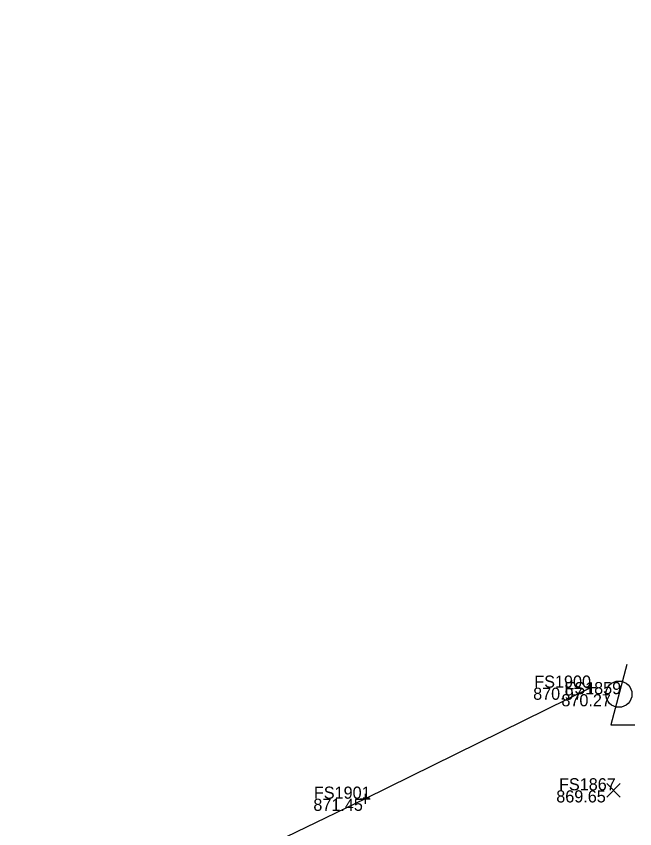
# Model space of a CAD drawing. Extents: x 1479420 to 1479833, y 379731 to 380103.
# Drawn here: x 1479739 to 1479800.3, y 380019.2 to 380099.7 of the extents above; entities that cross this region are included whole.
import ezdxf

# ---------------------------------------------------------------- set-up
doc = ezdxf.new("R2010")
doc.units = 0
for name, color, linetype in [('LT_X_Poles', 7, 'Continuous'), ('PV_X_Curb', 7, 'Continuous'), ('SV_X_Random_Point', 7, 'Continuous'), ('SV_X_Shot_Marker', 7, 'Continuous'), ('SV_X_Text_Elevation', 7, 'Continuous'), ('SV_X_Text_Name', 7, 'Continuous')]:
    doc.layers.add(name, color=color, linetype=linetype)

msp = doc.modelspace()

# ---------------------------------------------------------------- linework, layer by layer
at = {"layer": 'LT_X_Poles'}
msp.add_lwpolyline([(1479799.544, 380035.497), (1479797.969, 380029.512), (1479800.332, 380029.512)], dxfattribs=at)
msp.add_circle((1479798.757, 380032.544), 1.3, dxfattribs=at)
at = {"layer": 'PV_X_Curb'}
msp.add_lwpolyline([(1479795.994, 380033.189), (1479773.609, 380022.189), (1479753.08, 380012.28), (1479732.582, 380002.187), (1479709.578, 379990.944), (1479686.038, 379979.568), (1479675.424, 379995.638), (1479673.845, 379997.042), (1479672.388, 379997.402), (1479671.072, 379997.477), (1479668.749, 379997.507), (1479666.577, 379997.444), (1479665.261, 379997.435), (1479663.761, 379996.907), (1479662.621, 379996.118), (1479646.813, 379979.589), (1479631.39, 379994.413), (1479612.948, 380012.393), (1479594.615, 380030.048), (1479574.047, 380049.976), (1479559.355, 380064.639), (1479550.33, 380073.358), (1479530.481, 380092.839), (1479523.351, 380099.687)], dxfattribs=at)
at = {"layer": 'SV_X_Random_Point'}
for p, q in [((1479797.562, 380022.355), (1479798.896, 380023.69)), ((1479797.562, 380023.69), (1479798.896, 380022.355))]:
    msp.add_line(p, q, dxfattribs=at)
at = {"layer": 'SV_X_Shot_Marker'}
for p, q in [((1479795.494, 380033.189), (1479796.494, 380033.189)), ((1479795.994, 380033.689), (1479795.994, 380032.689)), ((1479795.994, 380033.189), (1479795.994, 380033.189)), ((1479773.609, 380022.689), (1479773.609, 380021.689)), ((1479773.109, 380022.189), (1479774.109, 380022.189)), ((1479773.609, 380022.189), (1479773.609, 380022.189))]:
    msp.add_line(p, q, dxfattribs=at)

# ---------------------------------------------------------------- texts
at = {"layer": 'SV_X_Text_Elevation'}
for s, p in [('870.97', (1479790.259, 380031.989)), ('870.27', (1479793.06, 380031.344)), ('869.65', (1479792.551, 380021.822)), ('871.45', (1479768.47, 380020.989))]:
    msp.add_text(s, height=1.2, dxfattribs=at).set_placement(p)
at = {"layer": 'SV_X_Text_Name'}
for s, p in [('FS1900', (1479790.373, 380033.189)), ('FS1859', (1479793.363, 380032.544)), ('FS1867', (1479792.825, 380023.022)), ('FS1901', (1479768.526, 380022.189))]:
    msp.add_text(s, height=1.2, dxfattribs=at).set_placement(p)

doc.saveas('drawing.dxf')
